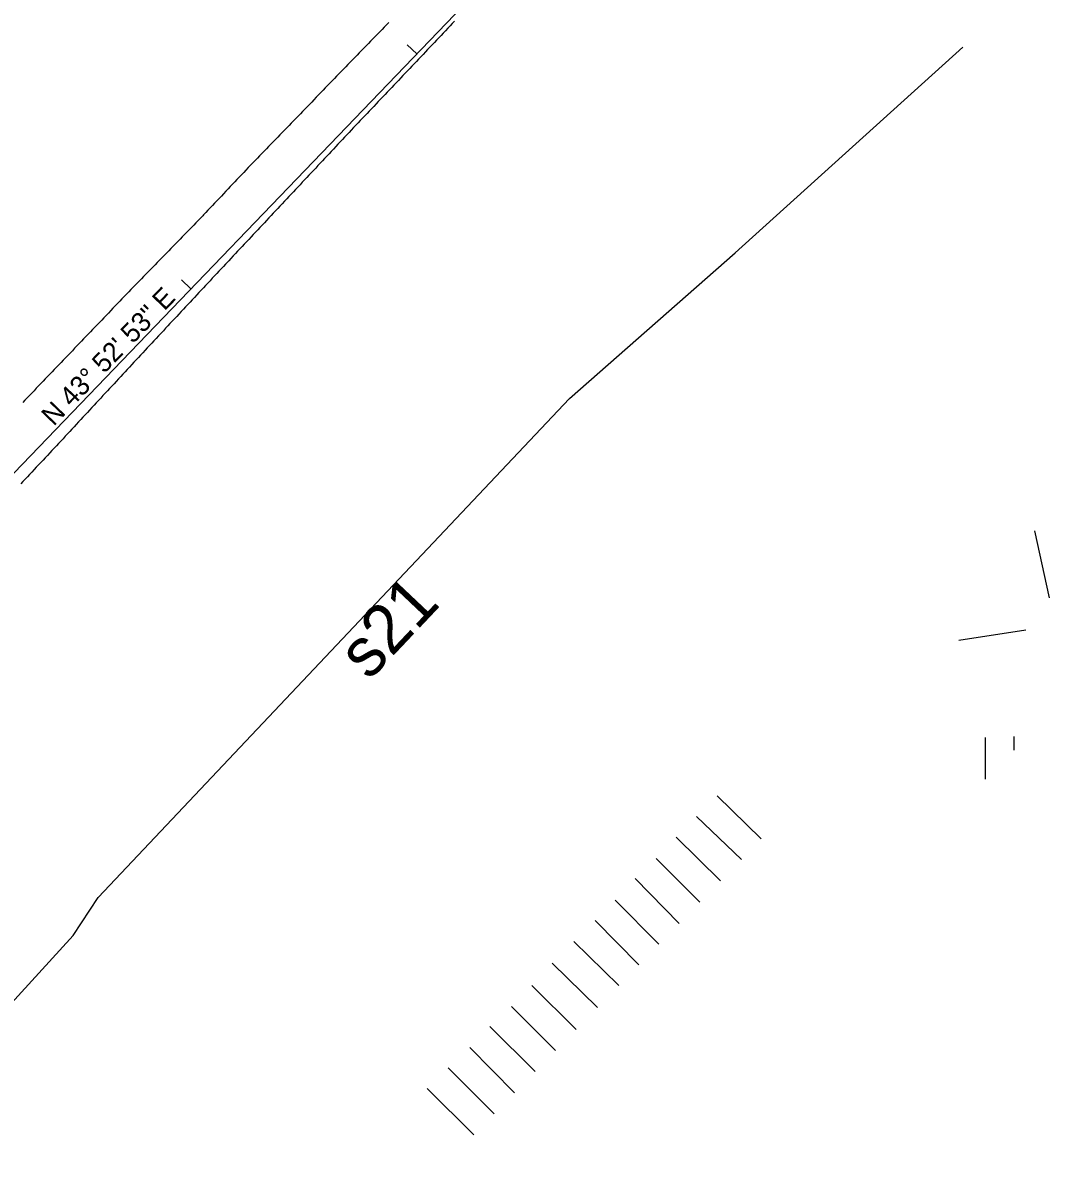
# Model space of a CAD drawing. Extents: x 205929 to 2357175, y -1785700 to 846739.
# Drawn here: x 2013114 to 2013428.9, y 820993.4 to 821344.1 of the extents above; entities that cross this region are included whole.
import ezdxf

# ---------------------------------------------------------------- set-up
doc = ezdxf.new("R2010")
doc.units = 0
for name, color, linetype in [('Default', 7, 'Continuous'), ('RD_EV_JTrib', 7, 'Continuous'), ('RD_EV_TX', 7, 'Continuous'), ('RD_HC_Cl', 7, 'Continuous'), ('RD_Sketch1', 7, 'Continuous')]:
    doc.layers.add(name, color=color, linetype=linetype)

# ---------------------------------------------------------------- blocks, each defined once
blk = doc.blocks.new('ARC0002L')
at = {"layer": 'Default'}
blk.add_lwpolyline([(-46.761, -51.417), (-19.138, -21.165), (-17.19, -18.199), (19.542, 20.689), (32.458, 32.041), (50.196, 48.051)], dxfattribs=at)

msp = doc.modelspace()

# ---------------------------------------------------------------- linework, layer by layer
at = {"layer": 'RD_HC_Cl'}
for p, q in [((2012957.62, 821046.27), (2013329.43, 821432.89)), ((2013234.89, 821334.58), (2013232, 821337.36)), ((2013165.57, 821262.5), (2013162.69, 821265.28))]:
    msp.add_line(p, q, dxfattribs=at)
at = {"layer": 'RD_Sketch1'}
for points in [[(2013246.48, 821344.62), (2013245.79, 821343.89), (2013245.11, 821343.16), (2013244.42, 821342.44), (2013243.73, 821341.71), (2013243.04, 821340.99), (2013242.35, 821340.26), (2013241.67, 821339.54), (2013240.98, 821338.81), (2013240.29, 821338.09), (2013239.6, 821337.36), (2013238.91, 821336.64), (2013238.23, 821335.91), (2013237.54, 821335.18), (2013236.85, 821334.46), (2013236.16, 821333.73), (2013235.47, 821333.01), (2013234.78, 821332.28), (2013234.1, 821331.56), (2013233.41, 821330.83), (2013232.72, 821330.11), (2013232.03, 821329.38), (2013232.03, 821329.38), (2013231.34, 821328.66), (2013230.65, 821327.93), (2013229.97, 821327.2), (2013229.28, 821326.48), (2013228.59, 821325.75), (2013227.9, 821325.03), (2013227.21, 821324.3), (2013226.52, 821323.58), (2013225.84, 821322.85), (2013225.15, 821322.13), (2013224.46, 821321.4), (2013223.77, 821320.68), (2013223.08, 821319.95), (2013222.39, 821319.23), (2013221.71, 821318.5), (2013221.02, 821317.77), (2013220.33, 821317.05), (2013219.64, 821316.32), (2013218.95, 821315.6), (2013218.26, 821314.87), (2013217.58, 821314.15), (2013216.89, 821313.42), (2013216.2, 821312.7), (2013215.51, 821311.97), (2013214.82, 821311.24), (2013214.14, 821310.52), (2013213.46, 821309.79), (2013212.77, 821309.06), (2013212.09, 821308.33), (2013211.4, 821307.6), (2013210.72, 821306.87), (2013210.03, 821306.14), (2013209.35, 821305.41), (2013208.67, 821304.68), (2013207.98, 821303.95), (2013207.3, 821303.22), (2013206.61, 821302.49), (2013205.93, 821301.77), (2013205.24, 821301.04), (2013204.56, 821300.31), (2013204.56, 821300.31), (2013203.88, 821299.58), (2013203.19, 821298.85), (2013202.51, 821298.12), (2013201.82, 821297.39), (2013201.14, 821296.66), (2013200.45, 821295.93), (2013199.77, 821295.2), (2013199.09, 821294.47), (2013198.4, 821293.74), (2013197.72, 821293.01), (2013197.03, 821292.29), (2013196.35, 821291.56), (2013195.66, 821290.83), (2013194.98, 821290.1), (2013194.3, 821289.37), (2013193.61, 821288.64), (2013192.93, 821287.91), (2013192.24, 821287.18), (2013191.56, 821286.45), (2013190.87, 821285.72), (2013190.19, 821284.99), (2013189.51, 821284.26), (2013188.82, 821283.53), (2013188.14, 821282.8), (2013187.46, 821282.07), (2013186.77, 821281.34), (2013186.09, 821280.61), (2013185.4, 821279.88), (2013184.72, 821279.16), (2013184.04, 821278.43), (2013183.35, 821277.7), (2013182.67, 821276.97), (2013181.99, 821276.24), (2013181.3, 821275.51), (2013180.62, 821274.78), (2013179.93, 821274.05), (2013179.25, 821273.32), (2013178.57, 821272.59), (2013177.88, 821271.86), (2013177.2, 821271.13), (2013176.94, 821270.85), (2013176.26, 821270.12), (2013175.58, 821269.39), (2013174.89, 821268.66), (2013174.21, 821267.93), (2013173.53, 821267.2), (2013172.84, 821266.47), (2013172.16, 821265.74), (2013171.48, 821265.01), (2013170.8, 821264.28), (2013170.11, 821263.55), (2013169.43, 821262.82), (2013168.75, 821262.09), (2013168.06, 821261.36), (2013167.38, 821260.63), (2013166.7, 821259.9), (2013166.01, 821259.17), (2013165.33, 821258.44), (2013164.65, 821257.71), (2013163.97, 821256.98), (2013163.28, 821256.25), (2013162.6, 821255.52), (2013161.92, 821254.79), (2013161.23, 821254.06), (2013160.55, 821253.33), (2013159.87, 821252.6), (2013159.18, 821251.87), (2013158.5, 821251.14), (2013157.82, 821250.41), (2013157.14, 821249.68), (2013156.45, 821248.95), (2013155.77, 821248.22), (2013155.62, 821248.05), (2013154.94, 821247.32), (2013154.26, 821246.59), (2013153.58, 821245.86), (2013152.9, 821245.12), (2013152.22, 821244.39), (2013151.54, 821243.66), (2013150.85, 821242.93), (2013150.17, 821242.19), (2013149.49, 821241.46), (2013148.81, 821240.73), (2013148.13, 821240), (2013147.45, 821239.26), (2013146.77, 821238.53), (2013146.09, 821237.8), (2013145.41, 821237.07), (2013144.73, 821236.33), (2013144.05, 821235.6), (2013143.37, 821234.87), (2013142.69, 821234.13), (2013142.01, 821233.4), (2013141.33, 821232.67), (2013140.65, 821231.93), (2013139.97, 821231.2), (2013139.29, 821230.47), (2013138.61, 821229.74), (2013137.93, 821229), (2013137.25, 821228.27), (2013136.57, 821227.54), (2013135.89, 821226.8), (2013135.21, 821226.07), (2013134.53, 821225.34), (2013133.85, 821224.61), (2013133.16, 821223.87), (2013132.48, 821223.14), (2013131.8, 821222.41), (2013131.12, 821221.67), (2013130.44, 821220.94), (2013129.76, 821220.21), (2013129.08, 821219.47), (2013128.4, 821218.74), (2013127.72, 821218.01), (2013127.04, 821217.28), (2013126.36, 821216.54), (2013125.68, 821215.81), (2013125, 821215.08), (2013124.32, 821214.34), (2013123.64, 821213.61), (2013122.95, 821212.88), (2013122.27, 821212.15), (2013121.59, 821211.43), (2013120.9, 821210.7), (2013120.22, 821209.97), (2013119.53, 821209.24), (2013118.85, 821208.51), (2013118.17, 821207.78), (2013117.48, 821207.05), (2013116.8, 821206.32), (2013116.11, 821205.59), (2013115.43, 821204.86), (2013114.74, 821204.13), (2013114.06, 821203.4), (2013113.38, 821202.67)], [(2013226.33, 821344.23), (2013225.63, 821343.51), (2013224.94, 821342.8), (2013224.24, 821342.08), (2013223.54, 821341.36), (2013222.85, 821340.65), (2013222.15, 821339.93), (2013221.45, 821339.21), (2013220.75, 821338.49), (2013220.06, 821337.78), (2013219.36, 821337.06), (2013218.66, 821336.34), (2013217.97, 821335.63), (2013217.27, 821334.91), (2013216.57, 821334.19), (2013215.88, 821333.47), (2013215.18, 821332.76), (2013214.48, 821332.04), (2013213.79, 821331.32), (2013213.09, 821330.6), (2013212.39, 821329.89), (2013211.7, 821329.17), (2013211, 821328.45), (2013210.3, 821327.74), (2013209.61, 821327.02), (2013208.91, 821326.3), (2013208.21, 821325.58), (2013207.52, 821324.86), (2013206.83, 821324.14), (2013206.13, 821323.42), (2013205.44, 821322.7), (2013204.74, 821321.99), (2013204.05, 821321.27), (2013203.35, 821320.55), (2013202.66, 821319.83), (2013201.96, 821319.11), (2013201.27, 821318.39), (2013200.57, 821317.67), (2013199.88, 821316.95), (2013199.18, 821316.23), (2013198.49, 821315.51), (2013197.79, 821314.79), (2013197.1, 821314.08), (2013196.4, 821313.36), (2013195.71, 821312.64), (2013195.01, 821311.92), (2013194.32, 821311.2), (2013193.62, 821310.48), (2013192.93, 821309.76), (2013192.23, 821309.04), (2013191.54, 821308.32), (2013190.84, 821307.6), (2013190.15, 821306.88), (2013189.45, 821306.16), (2013188.76, 821305.45), (2013188.06, 821304.73), (2013187.37, 821304.01), (2013186.67, 821303.29), (2013185.98, 821302.57), (2013185.28, 821301.85), (2013184.59, 821301.13), (2013183.89, 821300.41), (2013183.2, 821299.69), (2013182.5, 821298.97), (2013181.81, 821298.25), (2013181.12, 821297.53), (2013180.43, 821296.81), (2013179.74, 821296.08), (2013179.06, 821295.35), (2013178.37, 821294.62), (2013177.69, 821293.9), (2013177, 821293.17), (2013176.31, 821292.44), (2013175.63, 821291.71), (2013174.94, 821290.99), (2013174.26, 821290.26), (2013173.57, 821289.53), (2013172.88, 821288.8), (2013172.2, 821288.08), (2013171.51, 821287.35), (2013170.82, 821286.62), (2013170.14, 821285.89), (2013169.45, 821285.17), (2013169.24, 821284.94), (2013168.54, 821284.23), (2013167.85, 821283.51), (2013167.15, 821282.79), (2013166.45, 821282.08), (2013165.75, 821281.36), (2013165.06, 821280.65), (2013164.36, 821279.93), (2013163.66, 821279.21), (2013162.96, 821278.5), (2013162.26, 821277.78), (2013161.57, 821277.06), (2013160.87, 821276.35), (2013160.17, 821275.63), (2013159.47, 821274.92), (2013158.78, 821274.2), (2013158.08, 821273.48), (2013157.38, 821272.77), (2013156.68, 821272.05), (2013155.99, 821271.33), (2013155.29, 821270.62), (2013154.59, 821269.9), (2013153.89, 821269.19), (2013153.2, 821268.47), (2013152.5, 821267.75), (2013151.8, 821267.04), (2013151.1, 821266.32), (2013150.4, 821265.6), (2013149.71, 821264.89), (2013149.01, 821264.17), (2013148.31, 821263.46), (2013147.9, 821263.04), (2013147.21, 821262.31), (2013146.52, 821261.59), (2013145.83, 821260.87), (2013145.14, 821260.15), (2013144.44, 821259.43), (2013143.75, 821258.7), (2013143.06, 821257.98), (2013142.37, 821257.26), (2013141.68, 821256.54), (2013140.98, 821255.82), (2013140.29, 821255.1), (2013139.6, 821254.37), (2013138.91, 821253.65), (2013138.22, 821252.93), (2013137.52, 821252.21), (2013136.83, 821251.49), (2013136.14, 821250.76), (2013135.45, 821250.04), (2013134.76, 821249.32), (2013134.06, 821248.6), (2013133.37, 821247.88), (2013132.68, 821247.15), (2013131.99, 821246.43), (2013131.3, 821245.71), (2013130.61, 821244.99), (2013129.91, 821244.27), (2013129.22, 821243.54), (2013128.53, 821242.82), (2013127.84, 821242.1), (2013127.15, 821241.38), (2013126.45, 821240.66), (2013125.76, 821239.93), (2013125.07, 821239.21), (2013124.38, 821238.49), (2013123.69, 821237.77), (2013122.99, 821237.05), (2013122.3, 821236.33), (2013121.61, 821235.6), (2013120.92, 821234.88), (2013120.23, 821234.16), (2013119.53, 821233.44), (2013118.84, 821232.72), (2013118.15, 821231.99), (2013117.46, 821231.27), (2013116.77, 821230.55), (2013116.07, 821229.83), (2013115.38, 821229.11), (2013114.69, 821228.38), (2013114, 821227.66)], [(2013424.48, 821188.31), (2013428.92, 821167.71)], [(2013421.81, 821157.75), (2013401.17, 821154.6)], [(2013409.26, 821124.91), (2013409.29, 821112.05)], [(2013418.1, 821125.13), (2013418.07, 821120.95)], [(2013340.58, 821093.75), (2013327.02, 821106.98)], [(2013334.49, 821087.45), (2013320.71, 821100.65)], [(2013328.11, 821080.86), (2013314.44, 821094.31)], [(2013321.78, 821074.33), (2013308.34, 821087.78)], [(2013315.41, 821067.81), (2013301.89, 821081.61)], [(2013309.17, 821061.43), (2013295.73, 821074.92)], [(2013303.05, 821055.12), (2013289.63, 821068.7)], [(2013296.92, 821048.77), (2013283.06, 821062.23)], [(2013276.48, 821055.59), (2013290.36, 821042.01)], [(2013283.8, 821035.28), (2013270.24, 821048.82)], [(2013263.93, 821042.29), (2013277.49, 821028.81)], [(2013271.21, 821022.37), (2013257.35, 821036.2)], [(2013251.16, 821029.72), (2013264.86, 821015.85)], [(2013258.63, 821009.43), (2013244.57, 821023.51)], [(2013238.06, 821017.21), (2013252.38, 821002.94)]]:
    msp.add_lwpolyline(points, dxfattribs=at)

# ---------------------------------------------------------------- block references
at = {"layer": 'RD_EV_JTrib', "xscale": 3.937007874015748, "yscale": 3.937007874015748}
msp.add_blockref('ARC0002L', (2013204.83, 821147.45), dxfattribs=at)

# ---------------------------------------------------------------- texts
at = {"layer": 'RD_EV_TX'}
msp.add_text('s21', height=15, rotation=46.6332, dxfattribs=at).set_placement((2013220.25, 821142.08))
at = {"layer": 'RD_HC_Cl'}
msp.add_text('N 43%%d 52\' 53" E', height=6, rotation=46.1187, dxfattribs=at).set_placement((2013123.48, 821220.18))

doc.saveas('drawing.dxf')
